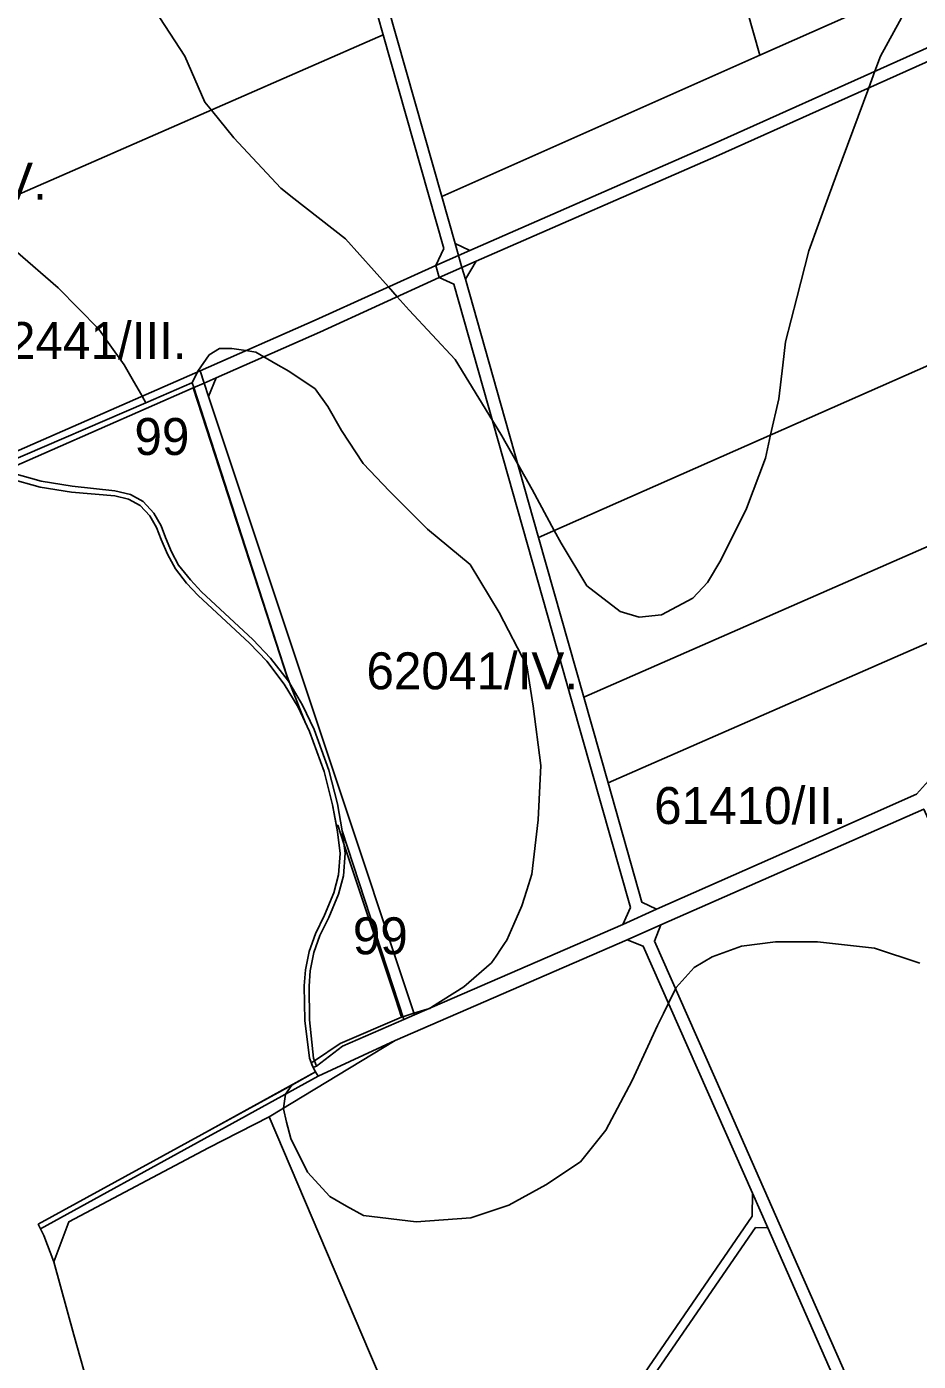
# Model space of a CAD drawing. Extents: x -522079 to -518792, y -1142400 to -1139961.
# Drawn here: x -521253 to -520891, y -1142050 to -1141508 of the extents above; entities that cross this region are included whole.
import ezdxf

# ---------------------------------------------------------------- set-up
doc = ezdxf.new("R2010")
doc.units = 0
for name, color, linetype in [('Hranice parcel', 7, 'Continuous'), ('Parcelní čísla', 7, 'Continuous'), ('Vnitřní kresba', 7, 'Continuous'), ('Značky bodu BP', 7, 'Continuous'), ('Značky budov', 7, 'Continuous')]:
    doc.layers.add(name, color=color, linetype=linetype)

msp = doc.modelspace()

# ---------------------------------------------------------------- linework, layer by layer
at = {"layer": 'Hranice parcel'}
for points in [[(-521147.68, -1141344.03), (-521149.23, -1141347.36), (-521109.72, -1141486.85), (-521084.21, -1141576.91), (-521078.78, -1141596.05), (-521077.42, -1141600.82), (-521086.66, -1141604.9), (-521083.41, -1141598.05), (-521107.96, -1141511.35), (-521142.48, -1141389.44), (-521153.82, -1141349.39), (-521156.76, -1141348.04), (-521157.35, -1141345.97), (-521146.08, -1141340.6)], [(-521077.42, -1141600.82), (-521076.03, -1141605.72), (-521085.26, -1141609.76), (-521086.66, -1141604.9)], [(-521079.3, -1141612.54), (-521085.26, -1141609.76), (-521076.03, -1141605.72), (-521074.66, -1141610.52), (-521058.67, -1141667), (-521044.98, -1141715.3), (-521026.62, -1141780.12), (-521016.76, -1141814.92), (-521003.04, -1141863.38), (-520997.06, -1141866.15), (-521010.77, -1141872.32), (-521007.67, -1141865.49), (-521031.39, -1141781.75)], [(-521257.85, -1141680.84), (-521182.3, -1141647.66), (-521180.65, -1141652.62), (-521185.06, -1141654.56), (-521261.42, -1141688.16), (-521266.74, -1141680.79)], [(-521185.06, -1141654.56), (-521180.65, -1141652.62), (-521178.83, -1141658.1), (-521128.33, -1141809.83), (-521095.32, -1141908.99), (-521099.58, -1141911), (-521124.58, -1141834.32), (-521126.54, -1141823.43), (-521130, -1141809.79), (-521136, -1141793.25), (-521140.73, -1141783.35), (-521146.44, -1141773.64)], [(-521009, -1141878.54), (-520995.39, -1141872.52), (-520997.93, -1141879.1), (-520967.25, -1141948.55), (-520939.85, -1142010.61), (-520905.36, -1142088.65), (-520874.16, -1142159.29), (-520870.13, -1142168.42), (-520873.11, -1142174.16), (-520875.14, -1142169.56), (-520880.4, -1142157.63), (-520924.06, -1142058.74), (-520951.97, -1141995.53), (-520958.2, -1141981.43), (-521002.46, -1141881.16)], [(-521135.45, -1141932.22), (-521134.44, -1141933.97), (-521171.94, -1141954.7), (-521180.62, -1141959.39), (-521247.07, -1141995.86), (-521247.93, -1141994.05), (-521181.6, -1141957.64)]]:
    msp.add_lwpolyline(points, close=True, dxfattribs=at)
msp.add_lwpolyline([(-520888.63, -1141825.55), (-520995.39, -1141872.52), (-521009, -1141878.54), (-521103.17, -1141919.44), (-521134.44, -1141933.97), (-521135.45, -1141932.22), (-521136.46, -1141930.46), (-521135.11, -1141929.87), (-521124.47, -1141921.72), (-521099.58, -1141911), (-521095.32, -1141908.99), (-521010.77, -1141872.32), (-520997.06, -1141866.15), (-520930.02, -1141836.55), (-520891.63, -1141819.53), (-520885.53, -1141812.75)], dxfattribs=at)
at = {"layer": 'Parcelní čísla'}
for points in [[(-520980.65, -1141429.68), (-520851.22, -1141372.34), (-520845.27, -1141393.64), (-520844.73, -1141395.54), (-520826.14, -1141462.3), (-520955.18, -1141519.6)], [(-521378.39, -1141629.5), (-521389.3, -1141621.72), (-521393.54, -1141617.98), (-521399.61, -1141612.42), (-521404.05, -1141606.86), (-521406.05, -1141602.85), (-521409.49, -1141593.05), (-521412.01, -1141585.06), (-521414.13, -1141574.69), (-521415.34, -1141566.3), (-521417.47, -1141538.2), (-521418.07, -1141529.55), (-521421, -1141521.26), (-521425.07, -1141514.17), (-521310.56, -1141462.49), (-521142.48, -1141389.44), (-521107.96, -1141511.35), (-521234.07, -1141566.44)], [(-520980.65, -1141429.68), (-520955.18, -1141519.6), (-521084.21, -1141576.91), (-521109.72, -1141486.85)], [(-520821.3, -1141482.16), (-520824.28, -1141488.21), (-520974.97, -1141555.99), (-521072.78, -1141598.79), (-521078.78, -1141596.05), (-521084.21, -1141576.91), (-520955.18, -1141519.6), (-520826.14, -1141462.3)], [(-520819.82, -1141495.44), (-520822.47, -1141493.04), (-520972.97, -1141560.63), (-521070.28, -1141603.2), (-521076.03, -1141605.72), (-521077.42, -1141600.82), (-521072.78, -1141598.79), (-520974.97, -1141555.99), (-520824.28, -1141488.21), (-520821.3, -1141482.16)], [(-520822.47, -1141493.04), (-520819.82, -1141495.44), (-520847.36, -1141628.04), (-520954.68, -1141675.43), (-521044.98, -1141715.3), (-521058.67, -1141667), (-521074.66, -1141610.52), (-521070.28, -1141603.2), (-520972.97, -1141560.63)], [(-521257.85, -1141680.84), (-521266.74, -1141680.79), (-521277.4, -1141677.06), (-521313.67, -1141663.71), (-521328.02, -1141658.46), (-521341.44, -1141652.02), (-521378.39, -1141629.5), (-521234.07, -1141566.44), (-521107.96, -1141511.35), (-521083.41, -1141598.05), (-521086.66, -1141604.9), (-521135.66, -1141627.18), (-521182.3, -1141647.66)], [(-521078.78, -1141596.05), (-521072.78, -1141598.79), (-521077.42, -1141600.82)], [(-521085.26, -1141609.76), (-521133.64, -1141631.93), (-521175.81, -1141650.49), (-521180.65, -1141652.62), (-521182.3, -1141647.66), (-521135.66, -1141627.18), (-521086.66, -1141604.9)], [(-521076.03, -1141605.72), (-521070.28, -1141603.2), (-521074.66, -1141610.52)], [(-521095.32, -1141908.99), (-521128.33, -1141809.83), (-521178.83, -1141658.1), (-521175.81, -1141650.49), (-521133.64, -1141631.93), (-521085.26, -1141609.76), (-521079.3, -1141612.54), (-521031.39, -1141781.75), (-521007.67, -1141865.49), (-521010.77, -1141872.32)], [(-521044.98, -1141715.3), (-520954.68, -1141675.43), (-520847.36, -1141628.04), (-520854, -1141657.98), (-520864.49, -1141709.14), (-521026.62, -1141780.12)], [(-521180.65, -1141652.62), (-521175.81, -1141650.49), (-521178.83, -1141658.1)], [(-521026.62, -1141780.12), (-520864.49, -1141709.14), (-520873.01, -1141751.95), (-521016.76, -1141814.92)], [(-520873.01, -1141751.95), (-520885.53, -1141812.75), (-520891.63, -1141819.53), (-520930.02, -1141836.55), (-520997.06, -1141866.15), (-521003.04, -1141863.38), (-521016.76, -1141814.92)], [(-520997.93, -1141879.1), (-520995.39, -1141872.52), (-520888.63, -1141825.55), (-520837.29, -1141940.33), (-520792.44, -1142040.74), (-520794.02, -1142043.2), (-520832.63, -1142100.89), (-520865.14, -1142158.06), (-520874.16, -1142159.29), (-520905.36, -1142088.65), (-520939.85, -1142010.61), (-520967.25, -1141948.55)], [(-521068.69, -1142151.23), (-521113.51, -1142046.12), (-521154.29, -1141950.51), (-521103.17, -1141919.44), (-521009, -1141878.54), (-521002.46, -1141881.16), (-520958.2, -1141981.43), (-520958.22, -1141990.78), (-521045.32, -1142117.79)], [(-521235.48, -1141993.03), (-521178.81, -1141962.98), (-521154.29, -1141950.51), (-521113.51, -1142046.12), (-521068.69, -1142151.23), (-521143.48, -1142258.25), (-521148.58, -1142258.19), (-521154.1, -1142249.25), (-521169.79, -1142225.11), (-521174.19, -1142217.64), (-521189.97, -1142191.57), (-521192.34, -1142183.35), (-521198.94, -1142162.11), (-521208.63, -1142126.99), (-521218.49, -1142092.03), (-521226.84, -1142062.52), (-521233.47, -1142038.91), (-521241.65, -1142009.35)], [(-520951.97, -1141995.53), (-520956.88, -1141995.37), (-521042.42, -1142119.65), (-521141.2, -1142261.95), (-521141.26, -1142270.03), (-521148.58, -1142258.19), (-521143.48, -1142258.25), (-521068.69, -1142151.23), (-521045.32, -1142117.79), (-520958.22, -1141990.78), (-520958.2, -1141981.43)], [(-521011.25, -1142185.11), (-521102.18, -1142315.9), (-521121.26, -1142296.3), (-521140.11, -1142271.9), (-521141.26, -1142270.03), (-521141.2, -1142261.95), (-521042.42, -1142119.65), (-520956.88, -1141995.37), (-520951.97, -1141995.53), (-520924.06, -1142058.74)]]:
    msp.add_lwpolyline(points, close=True, dxfattribs=at)
at = {"layer": 'Vnitřní kresba'}
msp.add_lwpolyline([(-521258.87, -1141689.08), (-521246.75, -1141692.49), (-521234.23, -1141694.42), (-521216.85, -1141696.44), (-521210.58, -1141697.9), (-521205.36, -1141700.71), (-521201.07, -1141705.38), (-521198.1, -1141710.58), (-521196.27, -1141715.36), (-521193.87, -1141721.1), (-521191.06, -1141726.58), (-521186.22, -1141732.52), (-521181.74, -1141737.31), (-521160.88, -1141756.78), (-521153.73, -1141764.26), (-521146.44, -1141773.64), (-521140.73, -1141783.35), (-521136, -1141793.25), (-521130, -1141809.79), (-521126.54, -1141823.43), (-521124.58, -1141834.32), (-521123.46, -1141843.47), (-521124.12, -1141852.65), (-521126.12, -1141860.01), (-521130.11, -1141869.48), (-521133.7, -1141876.9), (-521136.12, -1141883.81), (-521137.56, -1141891.19), (-521138.09, -1141897.36), (-521137.83, -1141911.01), (-521136.31, -1141926.58), (-521135.11, -1141929.87), (-521136.46, -1141930.46), (-521137.86, -1141926.67), (-521139.81, -1141911.29), (-521140.05, -1141897.31), (-521139.56, -1141890.84), (-521138.03, -1141883.29), (-521135.49, -1141876.13), (-521131.82, -1141868.6), (-521127.98, -1141859.55), (-521126.1, -1141852.28), (-521125.45, -1141843.51), (-521126.47, -1141834.73), (-521128.54, -1141823.8), (-521131.96, -1141810.32), (-521137.85, -1141793.99), (-521142.46, -1141784.23), (-521148.13, -1141774.78), (-521155.26, -1141765.5), (-521162.29, -1141758.22), (-521183.03, -1141738.83), (-521187.74, -1141733.86), (-521192.28, -1141728.07), (-521195.55, -1141722.03), (-521198.13, -1141716.1), (-521199.97, -1141711.28), (-521202.67, -1141706.57), (-521206.66, -1141702.29), (-521211.3, -1141699.75), (-521216.85, -1141698.47), (-521234.47, -1141696.96), (-521247.24, -1141694.95), (-521259.69, -1141691.44)], dxfattribs=at)
msp.add_lwpolyline([(-521103.17, -1141919.44), (-521154.29, -1141950.51), (-521178.81, -1141962.98), (-521235.48, -1141993.03), (-521241.65, -1142009.35), (-521245.74, -1141998.54), (-521247.07, -1141995.86), (-521180.62, -1141959.39), (-521171.94, -1141954.7), (-521134.44, -1141933.97)], close=True, dxfattribs=at)
at = {"layer": 'Značky bodu BP'}
for points in [[(-521200.71, -1141501.34), (-521188.48, -1141519.97), (-521180.32, -1141538.6), (-521177.71, -1141541.82), (-521168.54, -1141553.14), (-521149.52, -1141573.59), (-521144.26, -1141577.68), (-521123.24, -1141594.04), (-521105.85, -1141613.63), (-521102.34, -1141617.59), (-521097.42, -1141623.12), (-521078.85, -1141643.12), (-521063.66, -1141667.79), (-521059.82, -1141674.02), (-521053.47, -1141685.35), (-521047.59, -1141695.84), (-521038.6, -1141712.48), (-521035.81, -1141717.65), (-521025.39, -1141734.92), (-521011.8, -1141745.37), (-521004.1, -1141747.64), (-520995.04, -1141746.73), (-520982.36, -1141739.92), (-520976.47, -1141733.55), (-520971.03, -1141724.46), (-520960.61, -1141703.56), (-520952.91, -1141683.11), (-520950.79, -1141673.71), (-520947.47, -1141659.02), (-520945.88, -1141645.44), (-520944.76, -1141635.85), (-520940.16, -1141618.06), (-520935.24, -1141599.04), (-520927.38, -1141577.27), (-520923.92, -1141567.68), (-520911, -1141532.8), (-520908.52, -1141526.1), (-520906.25, -1141519.97), (-520893.11, -1141495.88)], [(-520893.11, -1141495.88), (-520906.25, -1141519.97), (-520908.52, -1141526.1), (-520911, -1141532.8), (-520923.92, -1141567.68), (-520927.38, -1141577.27), (-520935.24, -1141599.04), (-520940.16, -1141618.06), (-520944.76, -1141635.85), (-520945.88, -1141645.44), (-520947.47, -1141659.02), (-520950.79, -1141673.71), (-520952.91, -1141683.11), (-520960.61, -1141703.56), (-520971.03, -1141724.46), (-520976.47, -1141733.55), (-520982.36, -1141739.92), (-520995.04, -1141746.73), (-521004.1, -1141747.64), (-521011.8, -1141745.37), (-521025.39, -1141734.92), (-521035.81, -1141717.65), (-521038.6, -1141712.48), (-521047.59, -1141695.84), (-521053.47, -1141685.35), (-521059.82, -1141674.02), (-521063.66, -1141667.79), (-521078.85, -1141643.12), (-521097.42, -1141623.12), (-521102.34, -1141617.59), (-521105.85, -1141613.63), (-521123.24, -1141594.04), (-521144.26, -1141577.68), (-521149.52, -1141573.59), (-521168.54, -1141553.14), (-521177.71, -1141541.82), (-521180.32, -1141538.6), (-521188.48, -1141519.97), (-521200.71, -1141501.34)], [(-521257.35, -1141598.83), (-521239.84, -1141614.01), (-521223.41, -1141630.71), (-521219.52, -1141636.16), (-521213.03, -1141645.24), (-521209.81, -1141650.9), (-521206.47, -1141656.77), (-521206.12, -1141657.38), (-521205.78, -1141657.97), (-521204.3, -1141660.61), (-521262.08, -1141685.51)], [(-520890.31, -1141888.05), (-520908.69, -1141882.05), (-520931.77, -1141879.48), (-520948.87, -1141879.48), (-520962.55, -1141881.19), (-520974.52, -1141885.48), (-520981.78, -1141889.77), (-520989.05, -1141897.91), (-520989.35, -1141898.52), (-520992.24, -1141904.31), (-520994.31, -1141908.48), (-520996.74, -1141913.35), (-521007, -1141935.65), (-521017.69, -1141955.8), (-521027.95, -1141968.67), (-521042.05, -1141978.1), (-521057.01, -1141986.25), (-521072.4, -1141991.39), (-521094.63, -1141993.1), (-521116, -1141990.53), (-521122.84, -1141986.67), (-521129.68, -1141982.82), (-521138.66, -1141972.95), (-521145.49, -1141959.23), (-521147.16, -1141952.56), (-521148.49, -1141947.23), (-521148.45, -1141946.96), (-521147.63, -1141941.24), (-521145.11, -1141937.54), (-521135.45, -1141932.22), (-521136.46, -1141930.46), (-521136.69, -1141929.83), (-521136.78, -1141929.59), (-521137.06, -1141928.83), (-521137.18, -1141928.5), (-521136.24, -1141927.97), (-521135.89, -1141927.73), (-521125.48, -1141920.63), (-521100.56, -1141909.99), (-521099.97, -1141909.81), (-521095.51, -1141908.42), (-521090.17, -1141906.76), (-521089.05, -1141906.41), (-521088.36, -1141905.97), (-521075.24, -1141897.68), (-521063.99, -1141887.94), (-521062.15, -1141885.17), (-521060.15, -1141882.15), (-521058.77, -1141880.08), (-521057.85, -1141878.7), (-521054.99, -1141872.23), (-521051.72, -1141864.85), (-521049.67, -1141858.43), (-521047.62, -1141852.02), (-521045.07, -1141829.96), (-521044.04, -1141807.89), (-521047.11, -1141783.78), (-521049.67, -1141767.36), (-521060.92, -1141745.81), (-521072.69, -1141726.31), (-521090.08, -1141711.94), (-521105.42, -1141696.55), (-521116.16, -1141685.26), (-521124.86, -1141671.92), (-521130.48, -1141662.17), (-521135.6, -1141654.99), (-521146.34, -1141647.81), (-521151.49, -1141644.83), (-521156.44, -1141641.96), (-521159.64, -1141640.11), (-521163.66, -1141639.48), (-521169.36, -1141638.57), (-521174.47, -1141638.57), (-521178.56, -1141641.14), (-521183.17, -1141647.81), (-521183.32, -1141648.1), (-521185.53, -1141652.52), (-521185.64, -1141652.57), (-521204.3, -1141660.61), (-521205.78, -1141657.97), (-521206.12, -1141657.38), (-521206.47, -1141656.77), (-521209.81, -1141650.9), (-521213.03, -1141645.24), (-521219.52, -1141636.16), (-521223.41, -1141630.71), (-521239.84, -1141614.01), (-521257.35, -1141598.83)], [(-521262.08, -1141685.51), (-521204.3, -1141660.61), (-521185.64, -1141652.57), (-521185.53, -1141652.52), (-521184.89, -1141654.49), (-521147.1, -1141771.34), (-521145.67, -1141774.95), (-521139.63, -1141790.22), (-521137.85, -1141793.99), (-521142.46, -1141784.23), (-521148.13, -1141774.78), (-521155.26, -1141765.5), (-521162.29, -1141758.22), (-521183.03, -1141738.83), (-521187.74, -1141733.86), (-521192.28, -1141728.07), (-521195.55, -1141722.03), (-521198.13, -1141716.1), (-521199.97, -1141711.28), (-521202.67, -1141706.57), (-521206.66, -1141702.29), (-521211.3, -1141699.75), (-521216.85, -1141698.47), (-521234.47, -1141696.96), (-521247.24, -1141694.95), (-521259.69, -1141691.44)], [(-521226.84, -1142062.52), (-521233.47, -1142038.91), (-521241.65, -1142009.35), (-521245.74, -1141998.54), (-521247.07, -1141995.86), (-521247.93, -1141994.05), (-521181.6, -1141957.64), (-521145.11, -1141937.54), (-521147.63, -1141941.24), (-521148.45, -1141946.96), (-521148.49, -1141947.23), (-521147.16, -1141952.56), (-521145.49, -1141959.23), (-521138.66, -1141972.95), (-521129.68, -1141982.82), (-521122.84, -1141986.67), (-521116, -1141990.53), (-521094.63, -1141993.1), (-521072.4, -1141991.39), (-521057.01, -1141986.25), (-521042.05, -1141978.1), (-521027.95, -1141968.67), (-521017.69, -1141955.8), (-521007, -1141935.65), (-520996.74, -1141913.35), (-520994.31, -1141908.48), (-520992.24, -1141904.31), (-520989.35, -1141898.52), (-520989.05, -1141897.91), (-520981.78, -1141889.77), (-520974.52, -1141885.48), (-520962.55, -1141881.19), (-520948.87, -1141879.48), (-520931.77, -1141879.48), (-520908.69, -1141882.05), (-520890.31, -1141888.05)]]:
    msp.add_lwpolyline(points, dxfattribs=at)
for points in [[(-521045.07, -1141829.96), (-521047.62, -1141852.02), (-521049.67, -1141858.43), (-521051.72, -1141864.85), (-521054.99, -1141872.23), (-521057.85, -1141878.7), (-521058.77, -1141880.08), (-521060.15, -1141882.15), (-521062.15, -1141885.17), (-521063.99, -1141887.94), (-521075.24, -1141897.68), (-521088.36, -1141905.97), (-521089.05, -1141906.41), (-521090.17, -1141906.76), (-521095.51, -1141908.42), (-521099.97, -1141909.81), (-521100.56, -1141909.99), (-521102.92, -1141902.87), (-521123.93, -1141839.62), (-521126.43, -1141832.1), (-521126.93, -1141832.29), (-521128.54, -1141823.8), (-521131.96, -1141810.32), (-521137.85, -1141793.99), (-521139.63, -1141790.22), (-521145.67, -1141774.95), (-521147.1, -1141771.34), (-521184.89, -1141654.49), (-521185.53, -1141652.52), (-521183.32, -1141648.1), (-521183.17, -1141647.81), (-521178.56, -1141641.14), (-521174.47, -1141638.57), (-521169.36, -1141638.57), (-521163.66, -1141639.48), (-521159.64, -1141640.11), (-521156.44, -1141641.96), (-521151.49, -1141644.83), (-521146.34, -1141647.81), (-521135.6, -1141654.99), (-521130.48, -1141662.17), (-521124.86, -1141671.92), (-521116.16, -1141685.26), (-521105.42, -1141696.55), (-521090.08, -1141711.94), (-521072.69, -1141726.31), (-521060.92, -1141745.81), (-521049.67, -1141767.36), (-521047.11, -1141783.78), (-521044.04, -1141807.89)], [(-521137.86, -1141926.67), (-521139.81, -1141911.29), (-521140.05, -1141897.31), (-521139.56, -1141890.84), (-521138.03, -1141883.29), (-521135.49, -1141876.13), (-521131.82, -1141868.6), (-521127.98, -1141859.55), (-521126.1, -1141852.28), (-521125.45, -1141843.51), (-521126.47, -1141834.73), (-521128.54, -1141823.8), (-521126.93, -1141832.29), (-521126.43, -1141832.1), (-521123.93, -1141839.62), (-521102.92, -1141902.87), (-521100.56, -1141909.99), (-521125.48, -1141920.63), (-521135.89, -1141927.73), (-521136.24, -1141927.97), (-521137.18, -1141928.5), (-521137.06, -1141928.83)]]:
    msp.add_lwpolyline(points, close=True, dxfattribs=at)
at = {"layer": 'Značky budov'}
for points in [[(-521261.42, -1141688.16), (-521185.06, -1141654.56), (-521146.44, -1141773.64), (-521153.73, -1141764.26), (-521160.88, -1141756.78), (-521181.74, -1141737.31), (-521186.22, -1141732.52), (-521191.06, -1141726.58), (-521193.87, -1141721.1), (-521196.27, -1141715.36), (-521198.1, -1141710.58), (-521201.07, -1141705.38), (-521205.36, -1141700.71), (-521210.58, -1141697.9), (-521216.85, -1141696.44), (-521234.23, -1141694.42), (-521246.75, -1141692.49), (-521258.87, -1141689.08)], [(-521130.11, -1141869.48), (-521126.12, -1141860.01), (-521124.12, -1141852.65), (-521123.46, -1141843.47), (-521124.58, -1141834.32), (-521099.58, -1141911), (-521124.47, -1141921.72), (-521135.11, -1141929.87), (-521136.31, -1141926.58), (-521137.83, -1141911.01), (-521138.09, -1141897.36), (-521137.56, -1141891.19), (-521136.12, -1141883.81), (-521133.7, -1141876.9)]]:
    msp.add_lwpolyline(points, close=True, dxfattribs=at)

# ---------------------------------------------------------------- texts
at = {"layer": 'Značky bodu BP'}
for s, rotation, p in [('62041/IV.', 360, (-521330.37, -1141578.21)), ('62441/III.', 360, (-521271.4, -1141642.87)), ('99', 0, (-521208.94, -1141681.83)), ('62041/IV.', 0, (-521114.78, -1141776.93)), ('61410/II.', 0, (-520998.04, -1141831.6)), ('99', 360, (-521120.31, -1141884.48))]:
    msp.add_text(s, height=15, rotation=rotation, dxfattribs=at).set_placement(p)

doc.saveas('drawing.dxf')
